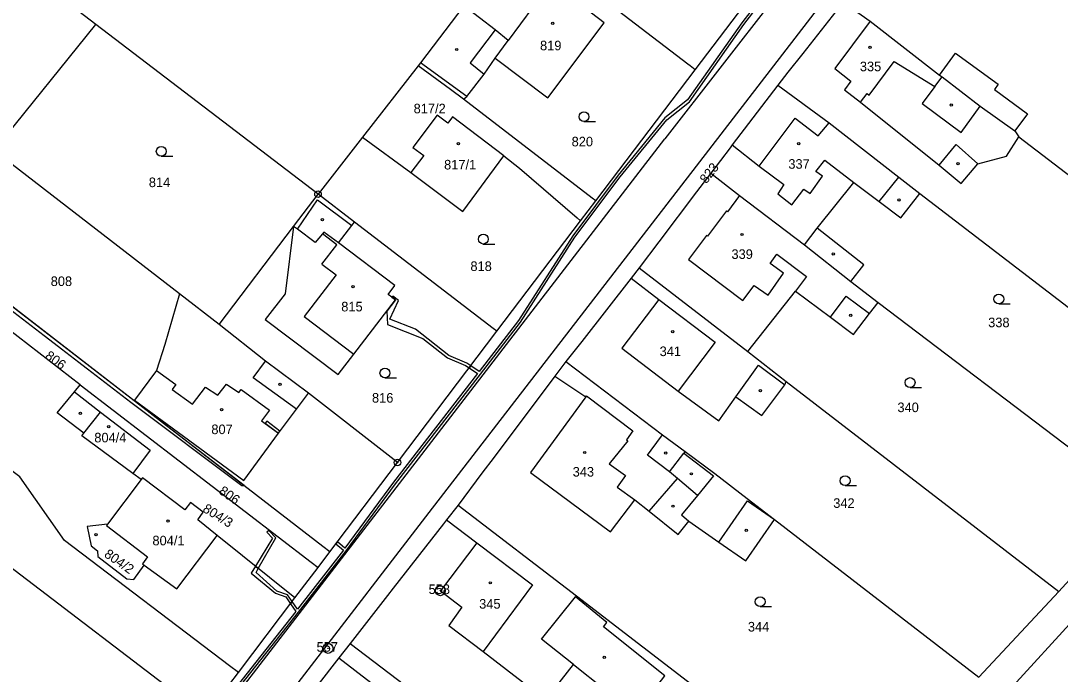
# Model space of a CAD drawing. Extents: x -587171 to -555306, y -1167727 to -1074732.
# Drawn here: x -560519.9 to -560361.6, y -1078035.5 to -1077935.9 of the extents above; entities that cross this region are included whole.
import ezdxf

# ---------------------------------------------------------------- set-up
doc = ezdxf.new("R2010")
doc.units = 0
for name, color, linetype in [('Hranice parcel', 7, 'Continuous'), ('Parcelní čísla', 7, 'Continuous'), ('Poz předměty', 7, 'Continuous'), ('Vnitřní kresba', 7, 'Continuous'), ('Věcná břemena k části', 7, 'Continuous'), ('Značky bodu BP', 7, 'Continuous'), ('Značky budov', 7, 'Continuous'), ('Značky kultur', 7, 'Continuous')]:
    doc.layers.add(name, color=color, linetype=linetype)

msp = doc.modelspace()

# ---------------------------------------------------------------- linework, layer by layer
at = {"layer": 'Hranice parcel'}
for p, q in [((-560508.49, -1077936.48), (-560526.41, -1077922.64)), ((-560417.21, -1077943.37), (-560402.14, -1077923.47)), ((-560394.67, -1077933.06), (-560390.55, -1077935.95)), ((-560523.98, -1077955.67), (-560508.49, -1077936.48)), ((-560474.65, -1077962.33), (-560508.49, -1077936.48)), ((-560459.42, -1077942.76), (-560467.89, -1077953.65)), ((-560432.35, -1077963.35), (-560417.21, -1077943.37)), ((-560467.89, -1077953.65), (-560474.65, -1077962.33)), ((-560467.89, -1077953.65), (-560460.49, -1077959.03)), ((-560367.95, -1077953.61), (-560326.86, -1077984.97)), ((-560495.73, -1077977.51), (-560523.98, -1077955.67)), ((-560478.38, -1077967.25), (-560474.65, -1077962.33)), ((-560469.07, -1077966.61), (-560474.65, -1077962.33)), ((-560382.99, -1077962.22), (-560338.03, -1077996.77)), ((-560434.66, -1077966.39), (-560432.35, -1077963.35)), ((-560489.68, -1077982.19), (-560478.38, -1077967.25)), ((-560447.4, -1077983.22), (-560434.66, -1077966.39)), ((-560510.85, -1077991.36), (-560536.32, -1077971.77)), ((-560425.75, -1077973.55), (-560426.98, -1077975.13)), ((-560425.75, -1077973.55), (-560409.21, -1077986.32)), ((-560393.53, -1077975.61), (-560389.36, -1077978.81)), ((-560489.68, -1077982.19), (-560495.73, -1077977.51)), ((-560389.36, -1077978.81), (-560349.43, -1078009.18)), ((-560462.54, -1078003.21), (-560447.4, -1077983.22)), ((-560436.89, -1077987.8), (-560438.57, -1077990.04)), ((-560409.21, -1077986.32), (-560403.35, -1077990.85)), ((-560403.35, -1077990.85), (-560361.85, -1078022.87)), ((-560511.75, -1077992.47), (-560510.85, -1077991.36)), ((-560472.84, -1078016.81), (-560462.54, -1078003.21)), ((-560501.58, -1078005.81), (-560502.83, -1078004.9)), ((-560501.58, -1078005.81), (-560506.69, -1078012.59)), ((-560453.33, -1078009.7), (-560455.09, -1078011.95)), ((-560453.33, -1078009.7), (-560435.3, -1078023.53)), ((-560361.85, -1078022.87), (-560349.43, -1078009.18)), ((-560405.12, -1078011.91), (-560374.01, -1078035.93)), ((-560478.18, -1078023.86), (-560490, -1078014.34)), ((-560474.65, -1078019.19), (-560472.84, -1078016.81)), ((-560478.18, -1078023.86), (-560474.65, -1078019.19)), ((-560486.78, -1078035.21), (-560478.18, -1078023.86)), ((-560435.44, -1078023.7), (-560435.3, -1078023.53)), ((-560435.3, -1078023.53), (-560392.57, -1078056.3)), ((-560374.01, -1078035.93), (-560361.85, -1078022.87)), ((-560491.9, -1078041.97), (-560486.78, -1078035.21))]:
    msp.add_line(p, q, dxfattribs=at)
for points in [[(-560364.68, -1077894.4), (-560366.71, -1077894.44), (-560368.49, -1077895.33), (-560369.63, -1077896.38), (-560417.05, -1077958.08), (-560457.78, -1078010.82), (-560494.61, -1078058.79), (-560557.78, -1078140.57), (-560603.03, -1078199.81), (-560610.79, -1078208.96)], [(-560417.21, -1077943.37), (-560417.98, -1077942.78), (-560418.34, -1077942.53), (-560443.96, -1077922.87)], [(-560452.48, -1077947.87), (-560451.99, -1077947.43), (-560449.35, -1077944.03), (-560447.67, -1077941.59), (-560439.65, -1077947.63), (-560431.05, -1077936.21), (-560434.08, -1077933.91), (-560433.31, -1077932.88), (-560436.2, -1077930.71), (-560437.94, -1077932.89), (-560440.05, -1077931.25), (-560445.69, -1077938.9), (-560447.68, -1077937.28), (-560452.43, -1077933.61)], [(-560452.43, -1077933.61), (-560459.05, -1077942.29), (-560459.42, -1077942.76)], [(-560394.67, -1077933.06), (-560400.84, -1077940.87), (-560403.11, -1077943.74), (-560404.65, -1077945.69)], [(-560390.55, -1077935.95), (-560395.94, -1077943.17), (-560393.5, -1077945.12), (-560394.46, -1077946.42), (-560392.02, -1077948.3), (-560380.08, -1077957.88), (-560376.72, -1077960.69), (-560374.15, -1077957.71), (-560369.8, -1077956.51), (-560367.95, -1077953.61)], [(-560390.55, -1077935.95), (-560380.02, -1077944.19), (-560379.62, -1077944.43), (-560373.84, -1077948.92), (-560368.52, -1077952.67), (-560367.95, -1077953.61)], [(-560452.48, -1077947.87), (-560454.46, -1077946.35), (-560459.42, -1077942.76)], [(-560404.65, -1077945.69), (-560411.57, -1077954.83), (-560411.91, -1077955.28), (-560414.82, -1077959.12)], [(-560404.65, -1077945.69), (-560396.82, -1077951.47), (-560386.21, -1077959.71), (-560382.99, -1077962.22)], [(-560432.35, -1077963.35), (-560432.9, -1077962.92), (-560452.48, -1077947.87)], [(-560446.33, -1077956.5), (-560454.15, -1077950.55), (-560454.87, -1077951.51), (-560456.53, -1077950.3), (-560460.21, -1077955.2), (-560458.55, -1077956.44), (-560460.49, -1077959.03)], [(-560486.78, -1078035.21), (-560488.13, -1078034.19), (-560513.25, -1078015.1), (-560520.04, -1078005.38), (-560582.32, -1077958.88), (-560584.72, -1077957.09)], [(-560460.49, -1077959.03), (-560452.61, -1077964.98), (-560446.33, -1077956.5)], [(-560446.33, -1077956.5), (-560443.97, -1077958.38), (-560435.19, -1077965.94), (-560434.66, -1077966.39)], [(-560414.82, -1077959.12), (-560416.99, -1077961.98), (-560422.74, -1077969.57), (-560425.75, -1077973.55)], [(-560414.82, -1077959.12), (-560410.48, -1077962.55), (-560400.59, -1077970.03), (-560393.53, -1077975.61)], [(-560393.53, -1077975.61), (-560391.53, -1077973.07), (-560398.64, -1077967.5), (-560393.04, -1077960.52), (-560389.21, -1077963.45), (-560385.92, -1077965.91), (-560382.99, -1077962.22)], [(-560478.38, -1077967.25), (-560479.66, -1077977.51), (-560482.71, -1077981.4), (-560471.6, -1077989.82), (-560469.17, -1077986.7), (-560462.86, -1077978.44), (-560463.98, -1077977.59), (-560462.93, -1077976.23), (-560471.53, -1077969.72), (-560469.48, -1077967.12), (-560469.07, -1077966.61)], [(-560447.4, -1077983.22), (-560447.96, -1077982.79), (-560469.07, -1077966.61)], [(-560472.84, -1078016.81), (-560473.89, -1078016), (-560534.57, -1077969.16)], [(-560426.98, -1077975.13), (-560434.5, -1077984.75), (-560436.89, -1077987.8)], [(-560426.98, -1077975.13), (-560422.75, -1077978.36), (-560428.38, -1077985.79), (-560419.81, -1077992.33), (-560413.62, -1077996.88), (-560411.04, -1077993.2), (-560407.06, -1077996.07), (-560403.55, -1077991.37), (-560403.35, -1077990.85)], [(-560495.73, -1077977.51), (-560497.99, -1077985.25), (-560499.23, -1077989.17), (-560502.57, -1077993.71), (-560485.94, -1078005.98), (-560480.65, -1077998.73), (-560477.91, -1077995.11), (-560476.09, -1077992.66)], [(-560409.21, -1077986.32), (-560401.95, -1077977.1), (-560396.62, -1077981.09), (-560393.13, -1077983.7), (-560390.66, -1077980.5), (-560389.36, -1077978.81)], [(-560476.09, -1077992.66), (-560482.62, -1077987.78), (-560489.68, -1077982.19)], [(-560436.89, -1077987.8), (-560422.18, -1077999), (-560418.75, -1078001.54), (-560414.24, -1078004.91), (-560409.31, -1078008.68), (-560405.12, -1078011.91)], [(-560438.57, -1077990.04), (-560447.85, -1078002.4), (-560449.69, -1078004.85), (-560453.33, -1078009.7)], [(-560438.57, -1077990.04), (-560433.89, -1077993.23), (-560442.27, -1078004.72), (-560430.1, -1078013.77), (-560426.39, -1078008.91), (-560424.2, -1078010.62), (-560419.82, -1078014.19), (-560418.16, -1078012.14), (-560413.6, -1078015.36), (-560409.52, -1078018.22), (-560405.12, -1078011.91)], [(-560502.83, -1078004.9), (-560510.63, -1077999.15), (-560510.32, -1077998.76), (-560514.35, -1077995.64), (-560511.75, -1077992.47)], [(-560511.75, -1077992.47), (-560507.77, -1077995.55), (-560500.19, -1078001.32), (-560502.83, -1078004.9)], [(-560510.85, -1077991.36), (-560475.71, -1078018.38), (-560474.65, -1078019.19)], [(-560462.54, -1078003.21), (-560463.51, -1078002.47), (-560476.09, -1077992.66)], [(-560491.9, -1078041.97), (-560493.04, -1078041.09), (-560493.28, -1078040.7), (-560522.7, -1078018.26), (-560541.97, -1078003.31)], [(-560490, -1078014.34), (-560492.96, -1078011.96), (-560492.15, -1078010.77), (-560494.07, -1078009.3), (-560494.93, -1078010.45), (-560501.37, -1078005.54), (-560501.58, -1078005.81)], [(-560506.69, -1078012.59), (-560509.78, -1078012.98), (-560509.19, -1078015.89), (-560508.24, -1078016.66), (-560508.16, -1078017.54), (-560503.76, -1078020.95), (-560502.7, -1078021.03), (-560501.12, -1078018.85)], [(-560506.69, -1078012.59), (-560506.86, -1078012.81), (-560500.63, -1078017.58), (-560501.4, -1078018.64), (-560501.12, -1078018.85)], [(-560455.09, -1078011.95), (-560455.56, -1078012.55), (-560463.19, -1078022.36), (-560464.05, -1078023.47), (-560469.75, -1078030.79)], [(-560455.09, -1078011.95), (-560450.47, -1078015.48), (-560456.02, -1078022.76), (-560452.76, -1078025.24), (-560454.72, -1078028.04), (-560449.52, -1078032.03), (-560439.98, -1078039.36), (-560435.77, -1078034), (-560426.32, -1078041.49), (-560421.86, -1078035.72), (-560431.17, -1078028.24), (-560430.65, -1078027.59), (-560435.44, -1078023.7)], [(-560501.12, -1078018.85), (-560496.14, -1078022.46), (-560490, -1078014.34)], [(-560469.75, -1078030.79), (-560471.46, -1078032.97), (-560477.83, -1078041.16), (-560478.62, -1078042.18), (-560479.9, -1078043.82)], [(-560469.75, -1078030.79), (-560455.55, -1078041.63), (-560447.77, -1078047.61)]]:
    msp.add_lwpolyline(points, dxfattribs=at)
at = {"layer": 'Poz předměty'}
msp.add_line((-560388.65, -1078058.97), (-560351.09, -1078017.82), dxfattribs=at)
at = {"layer": 'Vnitřní kresba'}
for p, q in [((-560392.71, -1077916.38), (-560421.83, -1077953.88)), ((-560447.68, -1077937.28), (-560451.49, -1077942.29)), ((-560447.67, -1077941.59), (-560445.69, -1077938.9)), ((-560380.02, -1077944.19), (-560377.58, -1077940.83)), ((-560377.58, -1077940.83), (-560371.09, -1077945.55)), ((-560451.99, -1077947.43), (-560459.05, -1077942.29)), ((-560451.49, -1077942.29), (-560449.35, -1077944.03)), ((-560390.72, -1077947.22), (-560386.9, -1077942.13)), ((-560386.9, -1077942.13), (-560380.72, -1077945.92)), ((-560380.72, -1077945.92), (-560379.62, -1077944.43)), ((-560380.72, -1077945.92), (-560382.66, -1077948.53)), ((-560371.09, -1077945.55), (-560371.62, -1077946.35)), ((-560371.62, -1077946.35), (-560366.6, -1077950.06)), ((-560392.02, -1077948.3), (-560391.04, -1077946.98)), ((-560391.04, -1077946.98), (-560390.72, -1077947.22)), ((-560382.66, -1077948.53), (-560376.7, -1077952.95)), ((-560376.7, -1077952.95), (-560373.84, -1077948.92)), ((-560407.48, -1077958.07), (-560402.01, -1077950.73)), ((-560402.01, -1077950.73), (-560398.48, -1077953.41)), ((-560366.6, -1077950.06), (-560368.52, -1077952.67)), ((-560398.48, -1077953.41), (-560396.82, -1077951.47)), ((-560462.74, -1078007.05), (-560421.83, -1077953.88)), ((-560411.57, -1077954.83), (-560407.48, -1077958.07)), ((-560380.08, -1077957.88), (-560377.49, -1077954.77)), ((-560377.49, -1077954.77), (-560374.15, -1077957.71)), ((-560398.85, -1077958.88), (-560397.45, -1077957.15)), ((-560397.45, -1077957.15), (-560393.04, -1077960.52)), ((-560407.48, -1077958.07), (-560403.74, -1077960.87)), ((-560397.85, -1077959.59), (-560398.85, -1077958.88)), ((-560403.74, -1077960.87), (-560404.65, -1077962.29)), ((-560399.73, -1077962.23), (-560397.85, -1077959.59)), ((-560389.21, -1077963.45), (-560386.21, -1077959.71)), ((-560404.65, -1077962.29), (-560402.48, -1077963.97)), ((-560402.48, -1077963.97), (-560400.69, -1077961.54)), ((-560400.69, -1077961.54), (-560399.73, -1077962.23)), ((-560477.77, -1077967.64), (-560474.71, -1077963.21)), ((-560474.71, -1077963.21), (-560469.48, -1077967.12)), ((-560410.48, -1077962.55), (-560412.27, -1077965.01)), ((-560412.46, -1077964.86), (-560415.34, -1077968.73)), ((-560412.27, -1077965.01), (-560412.46, -1077964.86)), ((-560477.77, -1077967.64), (-560478.38, -1077967.25)), ((-560475.06, -1077969.7), (-560477.77, -1077967.64)), ((-560473.97, -1077968.36), (-560475.06, -1077969.7)), ((-560473.77, -1077968.12), (-560473.97, -1077968.36)), ((-560471.53, -1077969.72), (-560473.77, -1077968.12)), ((-560415.48, -1077968.63), (-560418.21, -1077972.3)), ((-560415.34, -1077968.73), (-560415.48, -1077968.63)), ((-560400.59, -1077970.03), (-560398.64, -1077967.5)), ((-560405.82, -1077972.91), (-560404.78, -1077971.47)), ((-560404.78, -1077971.47), (-560400.29, -1077974.88)), ((-560474.05, -1077973.01), (-560471.9, -1077974.61)), ((-560418.21, -1077972.3), (-560409.96, -1077978.54)), ((-560403.75, -1077974.36), (-560405.82, -1077972.91)), ((-560471.9, -1077974.61), (-560476.77, -1077980.97)), ((-560406.11, -1077977.73), (-560403.75, -1077974.36)), ((-560400.29, -1077974.88), (-560401.95, -1077977.1)), ((-560409.96, -1077978.54), (-560408.24, -1077976.24)), ((-560408.24, -1077976.24), (-560406.11, -1077977.73)), ((-560396.62, -1077981.09), (-560394.22, -1077977.89)), ((-560394.22, -1077977.89), (-560390.66, -1077980.5)), ((-560422.75, -1077978.36), (-560414.16, -1077984.87)), ((-560476.77, -1077980.97), (-560469.17, -1077986.7)), ((-560414.16, -1077984.87), (-560419.81, -1077992.33)), ((-560484.51, -1077990.3), (-560482.62, -1077987.78)), ((-560499.23, -1077989.17), (-560496.31, -1077991.35)), ((-560411.04, -1077993.2), (-560407.56, -1077988.37)), ((-560407.56, -1077988.37), (-560403.55, -1077991.37)), ((-560477.91, -1077995.11), (-560484.51, -1077990.3)), ((-560496.31, -1077991.35), (-560496.85, -1077992.08)), ((-560496.85, -1077992.08), (-560493.78, -1077994.31)), ((-560493.78, -1077994.31), (-560491.79, -1077991.71)), ((-560491.79, -1077991.71), (-560489.92, -1077992.95)), ((-560489.92, -1077992.95), (-560488.58, -1077991.26)), ((-560488.58, -1077991.26), (-560486.72, -1077992.56)), ((-560486.72, -1077992.56), (-560486.35, -1077992.07)), ((-560486.35, -1077992.07), (-560482.06, -1077995.25)), ((-560433.89, -1077993.23), (-560433.78, -1077993.07)), ((-560433.78, -1077993.07), (-560426.7, -1077998.37)), ((-560510.32, -1077998.76), (-560507.77, -1077995.55)), ((-560482.06, -1077995.25), (-560483.24, -1077996.85)), ((-560483.24, -1077996.85), (-560480.65, -1077998.73)), ((-560426.7, -1077998.37), (-560427.66, -1077999.77)), ((-560427.46, -1077999.91), (-560430.3, -1078003.41)), ((-560427.66, -1077999.77), (-560427.46, -1077999.91)), ((-560423.93, -1078001.33), (-560422.18, -1077999)), ((-560424.48, -1078002.08), (-560423.93, -1078001.33)), ((-560421.15, -1078004.66), (-560424.48, -1078002.08)), ((-560421.15, -1078004.66), (-560418.94, -1078001.78)), ((-560418.75, -1078001.54), (-560418.94, -1078001.78)), ((-560418.94, -1078001.78), (-560414.42, -1078005.26)), ((-560430.3, -1078003.41), (-560428.52, -1078004.68)), ((-560427.82, -1078005.19), (-560429.1, -1078006.97)), ((-560428.52, -1078004.68), (-560427.82, -1078005.19)), ((-560419.89, -1078005.64), (-560421.15, -1078004.66)), ((-560424.2, -1078010.62), (-560419.89, -1078005.64)), ((-560416.88, -1078008.23), (-560419.89, -1078005.64)), ((-560414.42, -1078005.26), (-560416.88, -1078008.23)), ((-560499.23, -1078054.43), (-560462.74, -1078007.05)), ((-560429.1, -1078006.97), (-560426.39, -1078008.91)), ((-560416.88, -1078008.23), (-560419.32, -1078011.2)), ((-560413.6, -1078015.36), (-560409.26, -1078009.05)), ((-560409.26, -1078009.05), (-560405.12, -1078011.91)), ((-560419.32, -1078011.2), (-560418.16, -1078012.14)), ((-560450.47, -1078015.48), (-560442, -1078021.88)), ((-560442, -1078021.88), (-560449.52, -1078032.03)), ((-560440.62, -1078030.15), (-560435.44, -1078023.7)), ((-560435.77, -1078034), (-560440.62, -1078030.15)), ((-560471.46, -1078032.97), (-560466.59, -1078036.73))]:
    msp.add_line(p, q, dxfattribs=at)
msp.add_lwpolyline([(-560474.05, -1077973.01), (-560471.78, -1077970.02), (-560473.97, -1077968.36)], dxfattribs=at)
at = {"layer": 'Věcná břemena k části'}
for points in [[(-560553.09, -1078122.58), (-560548.55, -1078115.78), (-560538.37, -1078102.57), (-560529.92, -1078091.55), (-560522.59, -1078082.82), (-560511.69, -1078069.48), (-560507.12, -1078063.06), (-560491.36, -1078043.42), (-560477.61, -1078026.04), (-560470.36, -1078016.66), (-560462.85, -1078006.44), (-560449.91, -1077989.74), (-560443.81, -1077981.83), (-560435.52, -1077968.87), (-560428.63, -1077959.68), (-560421.53, -1077951), (-560418.1, -1077948.23), (-560409.79, -1077936.45), (-560400.51, -1077924.36)], [(-560400.85, -1077924.15), (-560410.12, -1077936.21), (-560418.39, -1077947.96), (-560421.82, -1077950.71), (-560428.94, -1077959.43), (-560435.85, -1077968.65), (-560444.14, -1077981.59), (-560450.11, -1077989.35), (-560451.4, -1077988.5), (-560451.64, -1077988.81), (-560450.36, -1077989.66), (-560463.17, -1078006.2), (-560470.55, -1078016.25), (-560471.68, -1078015.28), (-560471.92, -1078015.6), (-560470.79, -1078016.57), (-560477.76, -1078025.58), (-560478.58, -1078024.39), (-560478.84, -1078024.73), (-560478.02, -1078025.91), (-560491.55, -1078043.02)]]:
    msp.add_lwpolyline(points, dxfattribs=at)
for points in [[(-560521.65, -1077979.82), (-560503.16, -1077994.04), (-560486.23, -1078006.73), (-560485.89, -1078006.74), (-560497.04, -1077998.13), (-560524.91, -1077976.62), (-560527.47, -1077974.64), (-560527.56, -1077974.95)], [(-560454.91, -1077987.28), (-560452.19, -1077988.45), (-560451.64, -1077988.81), (-560451.4, -1077988.5), (-560452, -1077988.1), (-560454.71, -1077986.93), (-560459.81, -1077982.9), (-560463.72, -1077981.35), (-560462.41, -1077978.53), (-560463.28, -1077977.86), (-560463.4, -1077978.03), (-560462.86, -1077978.44), (-560464.18, -1077980.16), (-560464.09, -1077982.16), (-560458.67, -1077984.31)], [(-560482.7, -1077997.24), (-560480.65, -1077998.73), (-560480.44, -1077998.45), (-560482.45, -1077996.9)], [(-560481.57, -1078014.75), (-560484.19, -1078019.02), (-560483.74, -1078019.38), (-560481.07, -1078014.69), (-560482.13, -1078013.56), (-560482.43, -1078013.84)], [(-560481.11, -1078023.15), (-560479.55, -1078023.69), (-560478.84, -1078024.73), (-560478.58, -1078024.39), (-560479.3, -1078023.36), (-560480.91, -1078022.8), (-560484.08, -1078019.98), (-560483.74, -1078019.38), (-560484.19, -1078019.02), (-560484.84, -1078020.07)]]:
    msp.add_lwpolyline(points, close=True, dxfattribs=at)
at = {"layer": 'Značky bodu BP'}
for centre, radius in [((-560474.65, -1077962.33), 0.5), ((-560474.65, -1077962.33), 0.0303), ((-560462.54, -1078003.21), 0.5), ((-560462.54, -1078003.21), 0.0303), ((-560456.02, -1078022.76), 0.75), ((-560456.02, -1078022.76), 0.03), ((-560473.11, -1078031.55), 0.75), ((-560473.11, -1078031.55), 0.03)]:
    msp.add_circle(centre, radius, dxfattribs=at)
at = {"layer": 'Značky budov'}
for centre in [(-560438.9, -1077936.27), (-560453.52, -1077940.28), (-560390.59, -1077939.95), (-560378.23, -1077948.74), (-560453.28, -1077954.61), (-560401.44, -1077954.63), (-560377.18, -1077957.69), (-560386.18, -1077963.2), (-560473.98, -1077966.21), (-560410.08, -1077968.47), (-560396.18, -1077971.43), (-560469.3, -1077976.41), (-560393.52, -1077980.79), (-560420.63, -1077983.29), (-560480.43, -1077991.3), (-560407.28, -1077992.26), (-560510.83, -1077995.71), (-560489.32, -1077995.15), (-560506.52, -1077997.75), (-560434.04, -1078001.69), (-560421.69, -1078001.77), (-560417.78, -1078004.94), (-560420.6, -1078009.87), (-560497.48, -1078012.15), (-560508.44, -1078014.23), (-560409.44, -1078013.57), (-560448.41, -1078021.55), (-560431.07, -1078032.91)]:
    msp.add_circle(centre, 0.175, dxfattribs=at)
at = {"layer": 'Značky kultur'}
for p, q in [((-560434.15, -1077951.27), (-560432.4, -1077951.27)), ((-560498.52, -1077956.55), (-560496.77, -1077956.55)), ((-560449.48, -1077969.92), (-560447.73, -1077969.92)), ((-560370.98, -1077979.06), (-560369.23, -1077979.06)), ((-560464.46, -1077990.33), (-560462.71, -1077990.33)), ((-560384.49, -1077991.78), (-560382.74, -1077991.78)), ((-560394.38, -1078006.74), (-560392.63, -1078006.74)), ((-560407.32, -1078025.18), (-560405.57, -1078025.18))]:
    msp.add_line(p, q, dxfattribs=at)
for centre in [(-560434.15, -1077950.52), (-560498.52, -1077955.8), (-560449.48, -1077969.17), (-560370.98, -1077978.31), (-560464.46, -1077989.58), (-560384.49, -1077991.03), (-560394.38, -1078005.99), (-560407.32, -1078024.43)]:
    msp.add_circle(centre, 0.75, dxfattribs=at)

# ---------------------------------------------------------------- texts
at = {"layer": 'Parcelní čísla'}
for s, p in [('819', (-560440.84, -1077940.4)), ('335', (-560392.14, -1077943.59)), ('817/2', (-560460.09, -1077950)), ('820', (-560436.03, -1077955.04)), ('817/1', (-560455.45, -1077958.56)), ('337', (-560403.03, -1077958.45)), ('814', (-560500.41, -1077961.25)), ('339', (-560411.69, -1077972.19)), ('818', (-560451.44, -1077974.03)), ('808', (-560515.35, -1077976.32)), ('815', (-560471.11, -1077980.19)), ('338', (-560372.6, -1077982.6)), ('341', (-560422.63, -1077987)), ('816', (-560466.43, -1077994.09)), ('340', (-560386.42, -1077995.54)), ('804/4', (-560508.71, -1078000.15)), ('807', (-560490.89, -1077998.89)), ('343', (-560435.87, -1078005.36)), ('342', (-560396.19, -1078010.13)), ('804/1', (-560499.86, -1078015.84)), ('345', (-560450.11, -1078025.49)), ('344', (-560409.19, -1078028.97))]:
    msp.add_text(s, height=1.46, dxfattribs=at).set_placement(p)
for s, rotation, p in [('823', 52, (-560415.52, -1077960.83)), ('806', 324, (-560516.34, -1077987.24)), ('806', 325, (-560489.87, -1078007.86)), ('804/3', 328, (-560492.33, -1078010.62)), ('804/2', 325, (-560507.33, -1078017.48))]:
    msp.add_text(s, height=1.46, rotation=rotation, dxfattribs=at).set_placement(p)
at = {"layer": 'Značky bodu BP'}
for s, p in [('558', (-560457.81, -1078023.26)), ('557', (-560474.87, -1078032.05))]:
    msp.add_text(s, height=1.46, dxfattribs=at).set_placement(p)

doc.saveas('drawing.dxf')
